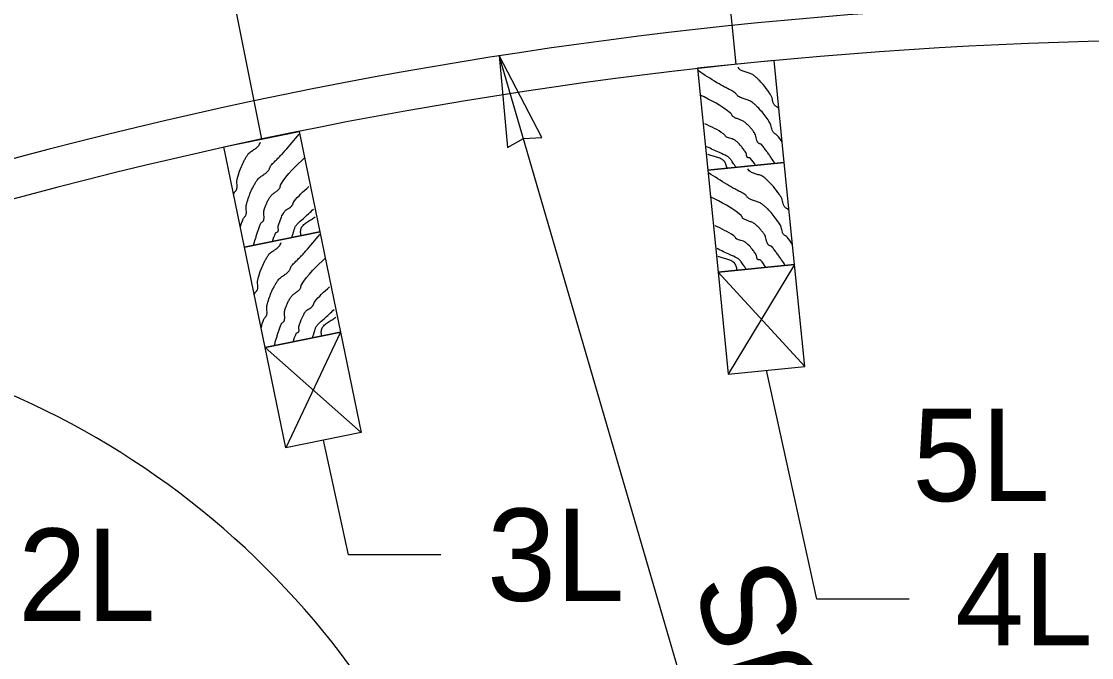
# Model space of a CAD drawing. Extents: x 1312564.2 to 1312581.5, y 1207298.4 to 1207352.6.
# Drawn here: x 1312567.233 to 1312568.157, y 1207307.422 to 1207307.972 of the extents above; entities that cross this region are included whole.
import ezdxf

# ---------------------------------------------------------------- set-up
doc = ezdxf.new("R2010")
doc.units = 0
for name, color, linetype in [('Level 13', 7, 'Continuous'), ('Level 14', 7, 'Continuous'), ('Level 15', 7, 'Continuous'), ('Level 20', 7, 'Continuous')]:
    doc.layers.add(name, color=color, linetype=linetype)

msp = doc.modelspace()

# ---------------------------------------------------------------- linework, layer by layer
at = {"layer": 'Level 13'}
for points in [[(1312567.8897056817, 1207307.8671528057), (1312567.885081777, 1207307.873476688), (1312567.8843999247, 1207307.8741197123), (1312567.8835707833, 1207307.8746167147), (1312567.8827362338, 1207307.875107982), (1312567.882038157, 1207307.8757338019), (1312567.8814469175, 1207307.8766584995), (1312567.881013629, 1207307.8776711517), (1312567.8804245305, 1207307.879855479), (1312567.8798781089, 1207307.8820771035), (1312567.8792600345, 1207307.8836416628), (1312567.8789816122, 1207307.8841263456), (1312567.8757612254, 1207307.8889096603), (1312567.872241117, 1207307.893458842), (1312567.8683405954, 1207307.8977026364), (1312567.866222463, 1207307.899687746), (1312567.8651170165, 1207307.9006422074), (1312567.8639789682, 1207307.9015697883), (1312567.862535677, 1207307.9025310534), (1312567.8609806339, 1207307.903284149), (1312567.8576910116, 1207307.9044327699), (1312567.8544215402, 1207307.905549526), (1312567.8521700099, 1207307.9066873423), (1312567.8514836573, 1207307.907168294), (1312567.8507403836, 1207307.9079056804), (1312567.8500859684, 1207307.9087609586), (1312567.849412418, 1207307.909595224), (1312567.8486117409, 1207307.910269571), (1312567.8448144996, 1207307.9124282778), (1312567.840936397, 1207307.914462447), (1312567.8370671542, 1207307.9165162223), (1312567.8332964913, 1207307.9187337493), (1312567.8173129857, 1207307.9288978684)], [(1312567.8868151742, 1207307.8960431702), (1312567.8860618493, 1207307.8970679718), (1312567.885748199, 1207307.8974166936), (1312567.8853801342, 1207307.897711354), (1312567.8845514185, 1207307.8982085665), (1312567.883717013, 1207307.8986997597), (1312567.8833418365, 1207307.8989868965), (1312567.8830182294, 1207307.8993250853), (1312567.8824257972, 1207307.9002491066), (1312567.8819919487, 1207307.9012614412), (1312567.8814030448, 1207307.9034458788), (1312567.8808575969, 1207307.9056680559), (1312567.8804780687, 1207307.9067275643), (1312567.8799616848, 1207307.9077176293), (1312567.8791795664, 1207307.908930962), (1312567.8783812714, 1207307.9101320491), (1312567.8731970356, 1207307.9170313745), (1312567.8692934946, 1207307.921272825), (1312567.8671840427, 1207307.923264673), (1312567.8660864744, 1207307.9242252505), (1312567.8649590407, 1207307.9251610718), (1312567.8635054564, 1207307.926103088), (1312567.8619038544, 1207307.9267926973), (1312567.8584907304, 1207307.9277811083), (1312567.855187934, 1207307.9288591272), (1312567.853724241, 1207307.9296607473), (1312567.85246373, 1207307.9307595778), (1312567.8512205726, 1207307.9322228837)], [(1312567.88351228, 1207307.848943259), (1312567.8802604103, 1207307.85377573), (1312567.8782995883, 1207307.8566166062), (1312567.8762819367, 1207307.859419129), (1312567.8742253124, 1207307.8621916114), (1312567.8721475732, 1207307.8649423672), (1312567.871831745, 1207307.8652570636), (1312567.8714482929, 1207307.8654944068), (1312567.8705666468, 1207307.8658378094), (1312567.869678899, 1207307.8661741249), (1312567.8689613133, 1207307.8667049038), (1312567.868603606, 1207307.8671885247), (1312567.868296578, 1207307.8677027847), (1312567.8678067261, 1207307.868806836), (1312567.867129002, 1207307.8712023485), (1312567.866482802, 1207307.873629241), (1312567.8657509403, 1207307.8753122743), (1312567.8654227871, 1207307.875825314), (1312567.863598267, 1207307.8782486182), (1312567.861628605, 1207307.8805596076), (1312567.8595031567, 1207307.8827366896), (1312567.8572112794, 1207307.8847582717), (1312567.8560349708, 1207307.8855625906), (1312567.8547556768, 1207307.8862002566), (1312567.8520330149, 1207307.8871955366), (1312567.849333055, 1207307.8881839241), (1312567.848082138, 1207307.8888129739), (1312567.8469455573, 1207307.8896052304), (1312567.8465041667, 1207307.8901793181), (1312567.8461879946, 1207307.8908802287), (1312567.8458526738, 1207307.8915604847), (1312567.845353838, 1207307.892072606), (1312567.8188036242, 1207307.9080730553)], [(1312567.866726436, 1207307.8472638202), (1312567.8621707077, 1207307.8533908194), (1312567.861929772, 1207307.8536021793), (1312567.8616222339, 1207307.853718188), (1312567.8608945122, 1207307.8537894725), (1312567.8601618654, 1207307.8538553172), (1312567.8595986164, 1207307.8541663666), (1312567.8594339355, 1207307.8543948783), (1312567.8592957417, 1207307.8546383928), (1312567.8590844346, 1207307.8551624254), (1312567.8588214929, 1207307.856302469), (1312567.8585797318, 1207307.8574584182), (1312567.858394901, 1207307.8580023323), (1312567.8581290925, 1207307.8585021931), (1312567.8571897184, 1207307.859888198), (1312567.8562231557, 1207307.8612613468), (1312567.854172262, 1207307.8639314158), (1312567.8506657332, 1207307.8676047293), (1312567.8500166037, 1207307.8681631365), (1312567.8493459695, 1207307.868703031), (1312567.8484159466, 1207307.8693015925), (1312567.8474110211, 1207307.869753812), (1312567.8452814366, 1207307.8704072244), (1312567.8431671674, 1207307.8710392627), (1312567.841717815, 1207307.8717254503), (1312567.8414947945, 1207307.8718703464), (1312567.8412781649, 1207307.8720259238), (1312567.8406840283, 1207307.872627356), (1312567.8401693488, 1207307.8733354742), (1312567.8396337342, 1207307.874018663), (1312567.8389767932, 1207307.8745453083), (1312567.822897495, 1207307.8832051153)], [(1312567.4219926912, 1207307.793751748), (1312567.42452009, 1207307.8011668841), (1312567.4249791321, 1207307.8019840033), (1312567.4256223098, 1207307.8027056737), (1312567.4262723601, 1207307.8034234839), (1312567.4267520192, 1207307.8042290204), (1312567.4270405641, 1207307.8052879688), (1312567.427152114, 1207307.8063837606), (1312567.427062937, 1207307.8086443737), (1312567.4269219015, 1207307.8109278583), (1312567.4270452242, 1207307.8126055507), (1312567.4271664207, 1207307.8131512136), (1312567.428813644, 1207307.8186773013), (1312567.4308167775, 1207307.8240693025), (1312567.433274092, 1207307.8292832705), (1312567.4347037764, 1207307.8318097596), (1312567.4354742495, 1207307.8330504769), (1312567.4362838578, 1207307.8342752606), (1312567.4373747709, 1207307.8356232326), (1312567.4386344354, 1207307.8368058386), (1312567.4414317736, 1207307.8388832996), (1312567.4442193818, 1207307.840924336), (1312567.4460290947, 1207307.8426818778), (1312567.446540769, 1207307.8433456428), (1312567.4470302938, 1207307.8442711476), (1312567.4473998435, 1207307.8452826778), (1312567.447793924, 1207307.8462798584), (1312567.448357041, 1207307.8471623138), (1312567.4513376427, 1207307.8503552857), (1312567.4544325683, 1207307.853453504), (1312567.45751319, 1207307.8565677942), (1312567.4604508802, 1207307.8598089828), (1312567.4726755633, 1207307.8742775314)], [(1312567.4161352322, 1207307.822189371), (1312567.4165486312, 1207307.8233922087), (1312567.4167440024, 1207307.8238186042), (1312567.4170074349, 1207307.8242096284), (1312567.417650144, 1207307.824931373), (1312567.4183000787, 1207307.8256490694), (1312567.4185725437, 1207307.826035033), (1312567.41878056, 1207307.826454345), (1312567.4190704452, 1207307.827513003), (1312567.4191826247, 1207307.8286086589), (1312567.4190932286, 1207307.830869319), (1312567.4189510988, 1207307.8331530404), (1312567.4189973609, 1207307.8342775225), (1312567.419194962, 1207307.8353765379), (1312567.4195796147, 1207307.836767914), (1312567.4199833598, 1207307.8381524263), (1312567.4228739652, 1207307.846283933), (1312567.4253348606, 1207307.8514965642), (1312567.4267542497, 1207307.8540268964), (1312567.4275153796, 1207307.855271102), (1312567.4283123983, 1207307.856500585), (1312567.429418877, 1207307.857833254), (1312567.430741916, 1207307.8589691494), (1312567.4337049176, 1207307.860930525), (1312567.436535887, 1207307.8629445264), (1312567.4376938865, 1207307.8641462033), (1312567.4385693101, 1207307.865570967), (1312567.4393194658, 1207307.8673384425)], [(1312567.8499806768, 1207307.845588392), (1312567.848359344, 1207307.8477721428), (1312567.8479989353, 1207307.8482727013), (1312567.8476464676, 1207307.8487875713), (1312567.8455408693, 1207307.8519484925), (1312567.84393959, 1207307.8538243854), (1312567.8419702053, 1207307.8552100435), (1312567.835490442, 1207307.858293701), (1312567.824704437, 1207307.863426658)], [(1312567.8420470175, 1207307.8447946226), (1312567.841605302, 1207307.8465351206), (1312567.841122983, 1207307.8482357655), (1312567.8404839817, 1207307.8497826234), (1312567.8400694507, 1207307.850462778), (1312567.8398320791, 1207307.8507733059), (1312567.8397050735, 1207307.8509204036), (1312567.8396393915, 1207307.8509918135), (1312567.8396059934, 1207307.8510269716), (1312567.8395891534, 1207307.8510444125), (1312567.8395722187, 1207307.8510617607), (1312567.8392583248, 1207307.8513646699), (1312567.8389280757, 1207307.8516515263), (1312567.8382217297, 1207307.8521802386), (1312567.8366481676, 1207307.8530797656), (1312567.8330377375, 1207307.8544240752), (1312567.8291527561, 1207307.8554989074), (1312567.8272360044, 1207307.8560615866), (1312567.8254050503, 1207307.8567084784)], [(1312567.4333351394, 1207307.7782180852), (1312567.434997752, 1207307.7838004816), (1312567.4360220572, 1207307.7870968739), (1312567.4371120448, 1207307.7903736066), (1312567.4382481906, 1207307.7936332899), (1312567.4394109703, 1207307.7968785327), (1312567.4396185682, 1207307.797273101), (1312567.4399137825, 1207307.7976140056), (1312567.4406528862, 1207307.7982047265), (1312567.441399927, 1207307.7987905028), (1312567.4419265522, 1207307.799511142), (1312567.4421237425, 1207307.8000794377), (1312567.4422634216, 1207307.800661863), (1312567.442401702, 1207307.8018617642), (1312567.4423341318, 1207307.804350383), (1312567.4422271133, 1207307.8068595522), (1312567.4424237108, 1207307.8086842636), (1312567.4425839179, 1207307.8092718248), (1312567.443602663, 1207307.8121289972), (1312567.4447934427, 1207307.814922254), (1312567.4461728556, 1207307.8176341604), (1312567.4477575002, 1207307.8202472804), (1312567.44864039, 1207307.8213658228), (1312567.4496712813, 1207307.8223560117), (1312567.4519731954, 1207307.824118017), (1312567.4542554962, 1207307.8258666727), (1312567.4552618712, 1207307.8268401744), (1312567.4561104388, 1207307.8279353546), (1312567.4563605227, 1207307.8286149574), (1312567.4564532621, 1207307.8293782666), (1312567.456570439, 1207307.8301275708), (1312567.4568938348, 1207307.8307651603), (1312567.4774636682, 1207307.8539558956)], [(1312567.898513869, 1207307.7791157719), (1312567.8938899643, 1207307.7854396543), (1312567.893208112, 1207307.786082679), (1312567.8923789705, 1207307.786579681), (1312567.8915444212, 1207307.7870709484), (1312567.8908463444, 1207307.787696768), (1312567.8902551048, 1207307.788621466), (1312567.8898218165, 1207307.7896341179), (1312567.889232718, 1207307.7918184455), (1312567.888686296, 1207307.7940400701), (1312567.8880682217, 1207307.7956046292), (1312567.8877897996, 1207307.7960893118), (1312567.8845694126, 1207307.8008726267), (1312567.881049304, 1207307.8054218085), (1312567.8771487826, 1207307.8096656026), (1312567.8750306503, 1207307.811650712), (1312567.873925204, 1207307.8126051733), (1312567.8727871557, 1207307.8135327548), (1312567.8713438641, 1207307.8144940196), (1312567.869788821, 1207307.8152471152), (1312567.8664991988, 1207307.816395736), (1312567.8632297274, 1207307.8175124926), (1312567.860978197, 1207307.8186503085), (1312567.8602918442, 1207307.8191312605), (1312567.8595485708, 1207307.8198686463), (1312567.8588941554, 1207307.820723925), (1312567.8582206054, 1207307.8215581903), (1312567.857419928, 1207307.8222325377), (1312567.853622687, 1207307.8243912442), (1312567.8497445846, 1207307.8264254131), (1312567.8458753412, 1207307.8284791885), (1312567.8421046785, 1207307.8306967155), (1312567.8261211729, 1207307.8408608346)], [(1312567.8956233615, 1207307.808006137), (1312567.8948700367, 1207307.809030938), (1312567.8945563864, 1207307.8093796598), (1312567.8941883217, 1207307.8096743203), (1312567.893359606, 1207307.8101715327), (1312567.8925252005, 1207307.8106627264), (1312567.8921500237, 1207307.8109498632), (1312567.8918264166, 1207307.8112880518), (1312567.8912339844, 1207307.8122120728), (1312567.8908001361, 1207307.8132244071), (1312567.890211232, 1207307.815408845), (1312567.889665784, 1207307.8176310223), (1312567.8892862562, 1207307.8186905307), (1312567.8887698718, 1207307.8196805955), (1312567.8879877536, 1207307.8208939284), (1312567.8871894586, 1207307.8220950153), (1312567.8820052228, 1207307.828994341), (1312567.8781016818, 1207307.8332357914), (1312567.8759922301, 1207307.8352276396), (1312567.8748946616, 1207307.8361882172), (1312567.8737672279, 1207307.8371240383), (1312567.8723136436, 1207307.8380660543), (1312567.8707120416, 1207307.8387556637), (1312567.8672989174, 1207307.8397440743), (1312567.8639961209, 1207307.8408220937), (1312567.8625324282, 1207307.8416237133), (1312567.861271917, 1207307.8427225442), (1312567.8600287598, 1207307.8441858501)], [(1312567.4498579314, 1207307.7816213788), (1312567.4523789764, 1207307.7888282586), (1312567.45254591, 1207307.7891018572), (1312567.4528048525, 1207307.789304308), (1312567.4534781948, 1207307.7895893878), (1312567.4541578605, 1207307.7898707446), (1312567.4546027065, 1207307.790335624), (1312567.45469174, 1207307.7906028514), (1312567.4547510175, 1207307.7908764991), (1312567.4547964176, 1207307.791439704), (1312567.45470738, 1207307.7926062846), (1312567.4545933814, 1207307.7937817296), (1312567.454607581, 1207307.7943560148), (1312567.454712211, 1207307.7949124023), (1312567.4551954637, 1207307.7965154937), (1312567.4557085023, 1207307.7981144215), (1312567.4568697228, 1207307.8012746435), (1312567.459121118, 1207307.8058265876), (1312567.4595741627, 1207307.8065531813), (1312567.4600532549, 1207307.807268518), (1312567.4607624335, 1207307.8081172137), (1312567.4615867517, 1207307.8088485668), (1312567.4634245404, 1207307.8101073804), (1312567.4652540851, 1207307.8113412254), (1312567.4664328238, 1207307.8124284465), (1312567.4666024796, 1207307.8126332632), (1312567.4667628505, 1207307.8128463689), (1312567.467150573, 1207307.8135976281), (1312567.467430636, 1207307.8144270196), (1312567.4677381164, 1207307.815238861), (1312567.4682080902, 1207307.8159374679), (1312567.4809728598, 1207307.828998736)], [(1312567.8923204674, 1207307.7609062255), (1312567.8890685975, 1207307.7657386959), (1312567.8871077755, 1207307.768579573), (1312567.885090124, 1207307.7713820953), (1312567.8830334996, 1207307.7741545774), (1312567.8809557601, 1207307.7769053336), (1312567.8806399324, 1207307.7772200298), (1312567.8802564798, 1207307.7774573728), (1312567.879374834, 1207307.7778007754), (1312567.8784870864, 1207307.778137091), (1312567.8777695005, 1207307.77866787), (1312567.8774117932, 1207307.779151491), (1312567.8771047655, 1207307.7796657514), (1312567.8766149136, 1207307.7807698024), (1312567.8759371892, 1207307.783165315), (1312567.8752909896, 1207307.7855922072), (1312567.8745591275, 1207307.7872752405), (1312567.8742309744, 1207307.7877882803), (1312567.8724064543, 1207307.7902115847), (1312567.870436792, 1207307.792522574), (1312567.868311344, 1207307.794699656), (1312567.866019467, 1207307.7967212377), (1312567.8648431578, 1207307.7975255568), (1312567.863563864, 1207307.7981632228), (1312567.8608412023, 1207307.799158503), (1312567.8581412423, 1207307.8001468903), (1312567.8568903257, 1207307.8007759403), (1312567.8557537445, 1207307.8015681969), (1312567.8553123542, 1207307.8021422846), (1312567.8549961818, 1207307.8028431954), (1312567.8546608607, 1207307.8035234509), (1312567.854162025, 1207307.804035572), (1312567.8276118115, 1207307.8200360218)], [(1312567.466341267, 1207307.7850165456), (1312567.4672375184, 1207307.787584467), (1312567.4674322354, 1207307.7881697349), (1312567.4676151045, 1207307.7887662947), (1312567.4686821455, 1207307.792411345), (1312567.4696510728, 1207307.7946794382), (1312567.4711175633, 1207307.796589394), (1312567.476382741, 1207307.8014652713), (1312567.485146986, 1207307.8095814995)], [(1312567.4741505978, 1207307.7866250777), (1312567.4740531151, 1207307.7884181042), (1312567.4740062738, 1207307.7901852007), (1312567.4741548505, 1207307.7918522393), (1312567.4743476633, 1207307.7926250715), (1312567.474481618, 1207307.792992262), (1312567.4745589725, 1207307.793170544), (1312567.4746003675, 1207307.7932582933), (1312567.4746217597, 1207307.7933018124), (1312567.4746326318, 1207307.793323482), (1312567.4746436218, 1207307.793345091), (1312567.4748528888, 1207307.793727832), (1312567.4750825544, 1207307.7941001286), (1312567.475599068, 1207307.794815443), (1312567.4768327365, 1207307.7961433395), (1312567.4798779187, 1207307.798503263), (1312567.4832655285, 1207307.800687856), (1312567.4849272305, 1207307.8017965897), (1312567.4864819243, 1207307.8029601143)], [(1312567.8755346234, 1207307.759226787), (1312567.8709788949, 1207307.7653537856), (1312567.8707379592, 1207307.7655651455), (1312567.870430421, 1207307.765681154), (1312567.8697026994, 1207307.765752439), (1312567.8689700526, 1207307.7658182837), (1312567.8684068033, 1207307.7661293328), (1312567.8682421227, 1207307.7663578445), (1312567.8681039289, 1207307.7666013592), (1312567.8678926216, 1207307.7671253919), (1312567.86762968, 1207307.7682654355), (1312567.8673879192, 1207307.7694213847), (1312567.8672030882, 1207307.769965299), (1312567.8669372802, 1207307.7704651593), (1312567.8659979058, 1207307.7718511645), (1312567.865031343, 1207307.773224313), (1312567.862980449, 1207307.775894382), (1312567.8594739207, 1207307.779567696), (1312567.8588247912, 1207307.780126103), (1312567.8581541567, 1207307.7806659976), (1312567.857224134, 1207307.781264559), (1312567.8562192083, 1207307.7817167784), (1312567.8540896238, 1207307.7823701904), (1312567.8519753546, 1207307.7830022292), (1312567.850526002, 1207307.783688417), (1312567.850302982, 1207307.7838333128), (1312567.850086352, 1207307.78398889), (1312567.8494922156, 1207307.7845903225), (1312567.8489775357, 1207307.7852984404), (1312567.8484419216, 1207307.7859816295), (1312567.8477849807, 1207307.7865082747), (1312567.8317056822, 1207307.7951680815)], [(1312567.4339845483, 1207307.7355319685), (1312567.4343979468, 1207307.736734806), (1312567.4345933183, 1207307.7371612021), (1312567.4348567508, 1207307.7375522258), (1312567.4354994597, 1207307.7382739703), (1312567.4361493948, 1207307.7389916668), (1312567.4364218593, 1207307.7393776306), (1312567.4366298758, 1207307.7397969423), (1312567.4369197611, 1207307.7408556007), (1312567.4370319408, 1207307.7419512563), (1312567.4369425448, 1207307.7442119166), (1312567.4368004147, 1207307.746495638), (1312567.4368466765, 1207307.7476201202), (1312567.4370442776, 1207307.7487191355), (1312567.4374289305, 1207307.7501105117), (1312567.4378326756, 1207307.7514950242), (1312567.4407232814, 1207307.7596265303), (1312567.4431841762, 1207307.764839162), (1312567.4446035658, 1207307.7673694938), (1312567.4453646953, 1207307.7686136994), (1312567.4461617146, 1207307.7698431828), (1312567.4472681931, 1207307.7711758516), (1312567.448591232, 1207307.7723117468), (1312567.4515542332, 1207307.7742731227), (1312567.454385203, 1207307.7762871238), (1312567.4555432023, 1207307.777488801), (1312567.4564186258, 1207307.7789135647), (1312567.4571687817, 1207307.7806810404)], [(1312567.4398420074, 1207307.7070943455), (1312567.4423694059, 1207307.7145094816), (1312567.4428284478, 1207307.715326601), (1312567.443471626, 1207307.7160482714), (1312567.444121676, 1207307.7167660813), (1312567.444601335, 1207307.7175716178), (1312567.44488988, 1207307.7186305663), (1312567.4450014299, 1207307.719726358), (1312567.444912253, 1207307.7219869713), (1312567.4447712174, 1207307.7242704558), (1312567.4448945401, 1207307.7259481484), (1312567.4450157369, 1207307.726493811), (1312567.44666296, 1207307.7320198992), (1312567.4486660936, 1207307.7374119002), (1312567.4511234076, 1207307.7426258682), (1312567.4525530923, 1207307.745152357), (1312567.4533235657, 1207307.7463930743), (1312567.4541331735, 1207307.7476178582), (1312567.4552240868, 1207307.7489658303), (1312567.4564837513, 1207307.7501484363), (1312567.4592810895, 1207307.752225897), (1312567.4620686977, 1207307.7542669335), (1312567.4638784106, 1207307.7560244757), (1312567.464390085, 1207307.7566882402), (1312567.46487961, 1207307.757613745), (1312567.4652491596, 1207307.7586252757), (1312567.46564324, 1207307.7596224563), (1312567.466206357, 1207307.7605049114), (1312567.4691869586, 1207307.7636978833), (1312567.4722818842, 1207307.7667961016), (1312567.4753625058, 1207307.769910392), (1312567.4783001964, 1207307.7731515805), (1312567.490524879, 1207307.7876201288)], [(1312567.858788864, 1207307.7575513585), (1312567.8571675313, 1207307.7597351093), (1312567.8568071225, 1207307.760235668), (1312567.8564546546, 1207307.7607505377), (1312567.8543490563, 1207307.763911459), (1312567.8527477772, 1207307.7657873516), (1312567.8507783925, 1207307.7671730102), (1312567.8442986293, 1207307.7702566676), (1312567.8335126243, 1207307.7753896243)], [(1312567.4511844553, 1207307.6915606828), (1312567.452847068, 1207307.697143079), (1312567.4538713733, 1207307.7004394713), (1312567.4549613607, 1207307.7037162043), (1312567.4560975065, 1207307.7069758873), (1312567.4572602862, 1207307.7102211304), (1312567.457467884, 1207307.7106156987), (1312567.4577630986, 1207307.7109566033), (1312567.458502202, 1207307.711547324), (1312567.459249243, 1207307.7121331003), (1312567.4597758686, 1207307.7128537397), (1312567.4599730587, 1207307.7134220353), (1312567.4601127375, 1207307.7140044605), (1312567.4602510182, 1207307.7152043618), (1312567.460183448, 1207307.7176929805), (1312567.4600764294, 1207307.7202021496), (1312567.4602730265, 1207307.722026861), (1312567.4604332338, 1207307.7226144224), (1312567.4614519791, 1207307.7254715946), (1312567.4626427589, 1207307.7282648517), (1312567.4640221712, 1207307.7309767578), (1312567.465606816, 1207307.733589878), (1312567.466489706, 1207307.7347084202), (1312567.4675205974, 1207307.7356986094), (1312567.469822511, 1207307.7374606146), (1312567.4721048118, 1207307.7392092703), (1312567.4731111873, 1207307.7401827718), (1312567.473959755, 1207307.741277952), (1312567.4742098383, 1207307.7419575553), (1312567.4743025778, 1207307.742720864), (1312567.4744197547, 1207307.7434701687), (1312567.4747431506, 1207307.7441077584), (1312567.495312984, 1207307.767298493)], [(1312567.8508552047, 1207307.7567575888), (1312567.8504134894, 1207307.758498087), (1312567.8499311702, 1207307.7601987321), (1312567.849292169, 1207307.7617455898), (1312567.8488776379, 1207307.7624257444), (1312567.8486402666, 1207307.762736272), (1312567.8485132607, 1207307.7628833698), (1312567.8484475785, 1207307.76295478), (1312567.8484141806, 1207307.762989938), (1312567.8483973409, 1207307.7630073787), (1312567.8483804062, 1207307.7630247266), (1312567.8480665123, 1207307.763327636), (1312567.8477362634, 1207307.7636144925), (1312567.8470299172, 1207307.7641432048), (1312567.8454563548, 1207307.7650427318), (1312567.8418459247, 1207307.7663870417), (1312567.8379609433, 1207307.7674618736), (1312567.8360441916, 1207307.768024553), (1312567.8342132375, 1207307.7686714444)], [(1312567.4677072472, 1207307.6949639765), (1312567.4702282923, 1207307.702170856), (1312567.4703952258, 1207307.702444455), (1312567.4706541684, 1207307.7026469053), (1312567.4713275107, 1207307.7029319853), (1312567.4720071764, 1207307.703213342), (1312567.4724520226, 1207307.703678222), (1312567.4725410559, 1207307.703945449), (1312567.4726003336, 1207307.7042190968), (1312567.4726457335, 1207307.7047823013), (1312567.4725566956, 1207307.7059488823), (1312567.4724426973, 1207307.7071243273), (1312567.472456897, 1207307.7076986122), (1312567.4725615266, 1207307.7082550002), (1312567.4730447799, 1207307.709858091), (1312567.4735578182, 1207307.7114570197), (1312567.4747190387, 1207307.7146172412), (1312567.476970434, 1207307.7191691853), (1312567.4774234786, 1207307.7198957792), (1312567.4779025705, 1207307.720611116), (1312567.4786117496, 1207307.7214598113), (1312567.4794360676, 1207307.7221911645), (1312567.4812738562, 1207307.7234499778), (1312567.4831034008, 1207307.7246838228), (1312567.48428214, 1207307.7257710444), (1312567.4844517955, 1207307.7259758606), (1312567.4846121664, 1207307.7261889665), (1312567.484999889, 1207307.7269402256), (1312567.4852799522, 1207307.7277696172), (1312567.485587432, 1207307.7285814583), (1312567.4860574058, 1207307.7292800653), (1312567.4988221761, 1207307.7423413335)], [(1312567.4841905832, 1207307.6983591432), (1312567.4850868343, 1207307.7009270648), (1312567.4852815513, 1207307.7015123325), (1312567.4854644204, 1207307.7021088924), (1312567.4865314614, 1207307.7057539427), (1312567.4875003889, 1207307.708022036), (1312567.488966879, 1207307.7099319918), (1312567.4942320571, 1207307.7148078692), (1312567.5029963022, 1207307.722924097)], [(1312567.4919999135, 1207307.6999676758), (1312567.4919024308, 1207307.701760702), (1312567.49185559, 1207307.7035277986), (1312567.4920041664, 1207307.7051948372), (1312567.4921969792, 1207307.7059676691), (1312567.4923309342, 1207307.7063348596), (1312567.4924082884, 1207307.7065131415), (1312567.4924496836, 1207307.706600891), (1312567.4924710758, 1207307.7066444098), (1312567.4924819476, 1207307.7066660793), (1312567.4924929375, 1207307.7066876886), (1312567.4927022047, 1207307.7070704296), (1312567.49293187, 1207307.7074427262), (1312567.493448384, 1207307.708158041), (1312567.4946820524, 1207307.7094859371), (1312567.4977272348, 1207307.7118458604), (1312567.5011148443, 1207307.714030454), (1312567.5027765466, 1207307.7151391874), (1312567.5043312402, 1207307.716302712)]]:
    msp.add_spline(points, degree=3, dxfattribs=at)
at = {"layer": 'Level 14'}
for p, q in [((1312567.8342615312, 1207307.7550973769), (1312567.9090644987, 1207307.6736631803)), ((1312567.9002563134, 1207307.761700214), (1312567.8430697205, 1207307.6670603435)), ((1312567.5083335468, 1207307.7033320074), (1312567.46122229, 1207307.6032943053)), ((1312567.443372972, 1207307.6899517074), (1312567.5261828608, 1207307.6166746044))]:
    msp.add_line(p, q, dxfattribs=at)
at = {"layer": 'Level 15'}
for p, q in [((1312567.8073100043, 1207308.3575831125), (1312567.8496425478, 1207307.9344728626)), ((1312567.355821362, 1207308.2924133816), (1312567.440154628, 1207307.8699566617)), ((1312567.9234343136, 1207306.9878162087), (1312567.6454897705, 1207307.942338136)), ((1312567.9194723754, 1207307.4725531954), (1312567.8760671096, 1207307.670361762)), ((1312567.5154052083, 1207307.5110801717), (1312567.4937025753, 1207307.609984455)), ((1312567.5951338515, 1207307.5110801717), (1312567.5154052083, 1207307.5110801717)), ((1312567.9992010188, 1207307.4725531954), (1312567.9194723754, 1207307.4725531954))]:
    msp.add_line(p, q, dxfattribs=at)
for points in [[(1312567.6454897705, 1207307.942338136), (1312567.6526419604, 1207307.8628080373), (1312567.6663826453, 1207307.8705874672), (1312567.6821517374, 1207307.8714009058)], [(1312567.882639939, 1207307.9377742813), (1312567.8166451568, 1207307.9311714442), (1312567.8254533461, 1207307.8431344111), (1312567.891448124, 1207307.8497372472)], [(1312567.4076743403, 1207307.863266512), (1312567.472634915, 1207307.8766468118), (1312567.490484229, 1207307.789989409), (1312567.425523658, 1207307.7766091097)], [(1312567.8914481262, 1207307.8497372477), (1312567.825453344, 1207307.8431344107), (1312567.8342615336, 1207307.755097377), (1312567.9002563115, 1207307.761700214)], [(1312567.425523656, 1207307.7766091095), (1312567.490484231, 1207307.7899894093), (1312567.508333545, 1207307.703332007), (1312567.4433729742, 1207307.6899517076)], [(1312567.9002563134, 1207307.761700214), (1312567.8342615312, 1207307.7550973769), (1312567.8430697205, 1207307.6670603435), (1312567.9090644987, 1207307.6736631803)], [(1312567.443372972, 1207307.6899517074), (1312567.5083335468, 1207307.7033320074), (1312567.5261828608, 1207307.6166746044), (1312567.46122229, 1207307.6032943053)]]:
    msp.add_lwpolyline(points, close=True, dxfattribs=at)
for centre, radius, start, end in [((1312568.259140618, 1207304.0100611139), 3.9794559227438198, 90.01657105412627, 113.93173117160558), ((1312568.2582266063, 1207304.0093876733), 3.946293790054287, 90.01657105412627, 113.93173117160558), ((1312566.9365166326, 1207306.9908537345), 0.7185570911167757, 246.6315280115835, 76.79679181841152)]:
    msp.add_arc(centre, radius, start, end, dxfattribs=at)

# ---------------------------------------------------------------- texts
at = {"layer": 'Level 20'}
for s, p in [('5L', (1312568.0020262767, 1207307.557361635)), ('3L', (1312567.6349981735, 1207307.4712158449)), ('2L', (1312567.2300563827, 1207307.4539672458)), ('4L', (1312568.0390653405, 1207307.4326888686))]:
    msp.add_text(s, height=0.07972865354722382, dxfattribs=at).set_placement(p)
msp.add_text('RADIUS', height=0.07972865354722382, rotation=106.23488333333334, dxfattribs=at).set_placement((1312568.001609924, 1207307.1241060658))

doc.saveas('drawing.dxf')
